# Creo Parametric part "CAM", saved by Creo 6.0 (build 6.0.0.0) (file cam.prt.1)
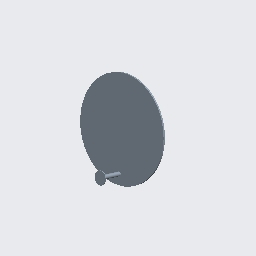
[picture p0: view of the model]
Units: millimeter Newton Second (mmNs); MM, TONNE, SECS

Created from: MMNS_PART_SOLID.PRT

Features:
  1. datum plane "RIGHT"
  2. datum plane "TOP"
  3. datum plane "FRONT"
  4. coordinate system
  5. sketch "Sketch 1"
  6. extrusion "Extrude 1"
  7. sketch "Sketch 2"
  8. extrusion "Extrude 2"
  9. sketch "Sketch 3"
  10. extrusion "Extrude 3"
  11. sketch "Sketch 4"
  12. extrusion "Extrude 4"
  13. datum plane "DTM1"

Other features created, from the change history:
  extruded cut "Extrude 2"
  sketch "Sketch 5"
  extrusion "Extrude 5"

Surfaces: 5 plane, 4 cylinder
